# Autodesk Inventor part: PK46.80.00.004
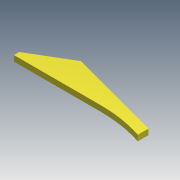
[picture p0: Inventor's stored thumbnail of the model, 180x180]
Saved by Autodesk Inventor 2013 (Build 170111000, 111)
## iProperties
Created: 2005-04
Part Number: PK46.80.00.004
Material: Steel, Mild
Document SubType Name: Modeling
Designer: salex
Manufacturer: Standard
Standards Organization: Custom
Density: 7.86 g/cm^3
Mass: 2233.21 g
Surface Area: 485.416 cm^2
Volume: 284.124 cm^3
Author: salex
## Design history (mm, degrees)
sketch "Эскиз1"
  geometry: L1 (0, 0)-(0, 15); L2 (0, 15)-(110, 80); L3 (110, 80)-(370, 10); L4 (370, 10)-(370, -20); L5 (243.826, 0)-(0, 0); A1 r 408 centre (243.826, -408) between (370, -20) and (243.826, 0)
  constraints: 10 end point, 2 point on circle, 1 centre point, 1 parallel, 1 perpendicular, 1 tangent, 1 vertical, 1 other
  dimensions: "d0" = 15 distance of L1.start L1.end; "d1" = 80 distance from line of L2.end L5; "d2" = 110 distance from line of L2.end L1; "d3" = 370 distance between parallel lines of L4 L1; "d4" = 408 radius of A1; "d5" = 20 distance from line of L4.end L5; "d6" = 30 distance of L3.end L4.end
extrude "Выдавливание1" new body sketch "Эскиз1" distance "d7" = 16; taper "d8" = 0 deg
body "Solid1"
